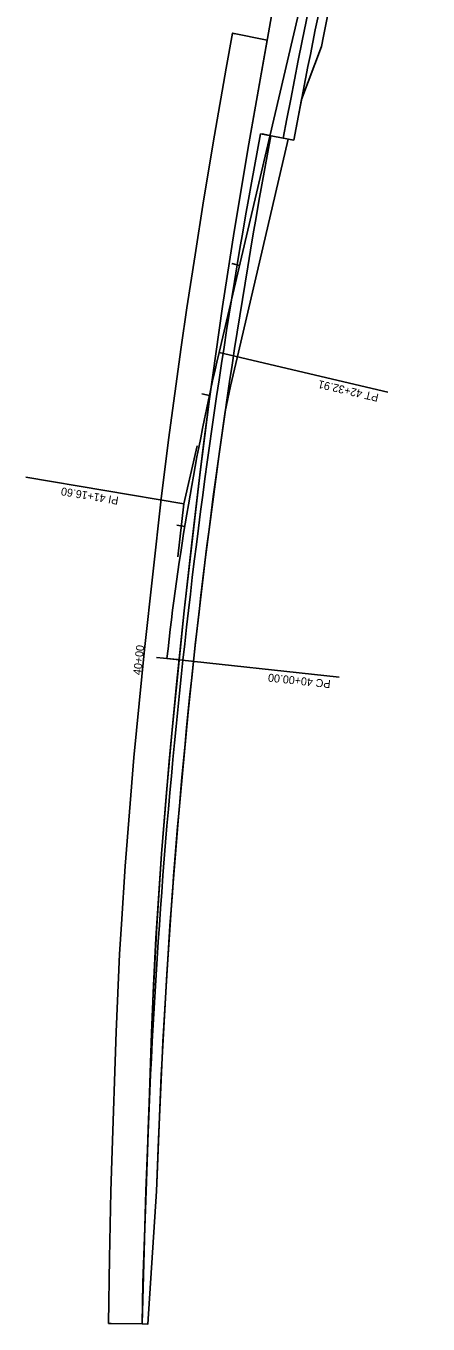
# Model space of a CAD drawing. Extents: x 1445613 to 1446340, y 2042797 to 2056486.
# Drawn here: x 1445613 to 1445914, y 2053367 to 2054340 of the extents above; entities that cross this region are included whole.
import ezdxf

# ---------------------------------------------------------------- set-up
doc = ezdxf.new("R2010")
doc.units = 0
for name, color, linetype in [('20', 7, 'Continuous'), ('Default', 7, 'Continuous'), ('R_Horz Alg', 7, 'Continuous'), ('R_Horz Alg Annot_Detour', 7, 'Continuous'), ('R_Horz Alg Stationing_Detour', 7, 'Continuous'), ('R_Proposed Road', 7, 'Continuous')]:
    doc.layers.add(name, color=color, linetype=linetype)

msp = doc.modelspace()

# ---------------------------------------------------------------- linework, layer by layer
at = {"layer": '20'}
msp.add_lwpolyline([(1445870.01, 2054502.76), (1445836.06, 2054332.52), (1445834.49, 2054324.75), (1445819.56, 2054285.22), (1445813.75, 2054254.63), (1445809.55, 2054255.41), (1445790.46, 2054173.78), (1445790.46, 2054173.78), (1445772.18, 2054095.64), (1445766.34, 2054070.08), (1445762.27, 2054051.24), (1445758, 2054021.18), (1445747.59, 2053941.98), (1445739.81, 2053875.52), (1445734.54, 2053825.65), (1445727.23, 2053747.07), (1445722.55, 2053688.35), (1445718.5, 2053629.06), (1445714.98, 2053566.67), (1445712.25, 2053505.21), (1445710.9, 2053466.32), (1445704.36, 2053366.78), (1445700.07, 2053366.83), (1445700.45, 2053397.66), (1445703.14, 2053466.51), (1445704.51, 2053512.96), (1445706.68, 2053573.23), (1445707.94, 2053608.8), (1445710.99, 2053665.29), (1445714.61, 2053719.31), (1445720.36, 2053788.85), (1445725.72, 2053846.27), (1445731.41, 2053901.64), (1445737.33, 2053952.64), (1445743.26, 2054003.64), (1445746.84, 2054032.1), (1445750.41, 2054060.55), (1445760.33, 2054129.83), (1445769.06, 2054186.05), (1445780.04, 2054251.75), (1445799.01, 2054359.02)], dxfattribs=at)
msp.add_lwpolyline([(1445674.84, 2053367.13), (1445700.07, 2053366.83), (1445700.45, 2053397.66), (1445703.14, 2053466.51), (1445704.94, 2053525.06), (1445707.1, 2053585.09), (1445708.55, 2053620.61), (1445710.38, 2053656.06), (1445714.61, 2053719.31), (1445718.26, 2053765.38), (1445722.45, 2053812.32), (1445731.41, 2053901.64), (1445743.26, 2054003.64), (1445750.41, 2054060.55), (1445760.33, 2054129.83), (1445769.06, 2054186.05), (1445780.04, 2054251.75), (1445790.18, 2054309.86), (1445793.67, 2054329.54), (1445767.66, 2054334.76), (1445763.07, 2054308.69), (1445754.39, 2054258.33), (1445746.12, 2054209.11), (1445739.66, 2054168.51), (1445733.55, 2054128.87), (1445729.18, 2054099.27), (1445719.7, 2054029.76), (1445714.16, 2053985.73), (1445701.84, 2053872.7), (1445693.83, 2053791.57), (1445687.38, 2053710.2), (1445684.44, 2053666.63), (1445683.14, 2053644.24), (1445680.49, 2053585.83), (1445677.31, 2053489.4), (1445676.65, 2053466.24), (1445675.65, 2053416.12)], close=True, dxfattribs=at)
at = {"layer": 'Default'}
for p, q in [((1445767.66, 2054334.76), (1445769.62, 2054334.36)), ((1445674.84, 2053367.13), (1445676.84, 2053367.1))]:
    msp.add_line(p, q, dxfattribs=at)
at = {"layer": 'R_Horz Alg'}
msp.add_line((1445757.73, 2054095.33), (1445849.12, 2054486.09), dxfattribs=at)
msp.add_arc((1447617.41, 2053660.4), 1909.86, 166.83661, 173.8239, dxfattribs=at)
at = {"layer": 'R_Horz Alg Annot_Detour'}
for q in [(1445741.36, 2054025.32), (1445726.9, 2053942.25)]:
    msp.add_line((1445731.18, 2053981.8), q, dxfattribs=at)
for points in [[(1445757.73, 2054095.33), (1445884.32, 2054065.73)], [(1445731.18, 2053981.8), (1445612.89, 2054001.95)], [(1445718.64, 2053865.88), (1445847.88, 2053851.89)]]:
    msp.add_lwpolyline(points, dxfattribs=at)
at = {"layer": 'R_Horz Alg Stationing_Detour'}
for points in [[(1445789.94, 2054259.4), (1445795.78, 2054258.03)], [(1445767.17, 2054162.03), (1445773.01, 2054160.66)], [(1445744.65, 2054064.49), (1445750.52, 2054063.23)], [(1445726.07, 2053965.93), (1445731.99, 2053964.97)], [(1445710.68, 2053866.74), (1445726.59, 2053865.02)]]:
    msp.add_lwpolyline(points, dxfattribs=at)
at = {"layer": 'R_Proposed Road'}
for p, q in [((1445788.69, 2054259.31), (1445813.75, 2054254.63)), ((1445702.9, 2053466.56), (1445700.07, 2053366.83)), ((1445710.9, 2053466.32), (1445704.36, 2053366.78)), ((1445700.07, 2053366.83), (1445704.36, 2053366.78))]:
    msp.add_line(p, q, dxfattribs=at)
for radius, start, end in [(5179.21, 164.16667, 169.4239), (5171.21, 166.10725, 169.4239), (5196.71, 169.4239, 178.2239), (5188.71, 169.4239, 178.2239)]:
    msp.add_arc((1450897.11, 2053305.5), radius, start, end, dxfattribs=at)

# ---------------------------------------------------------------- texts
at = {"layer": 'R_Horz Alg Annot_Detour'}
for s, rotation, p in [('PT 42+32.91', 166.83661, (1445877.79, 2054064.17)), ('PI 41+16.60', 170.33026, (1445682.66, 2053987.02)), ('PC 40+00.00', 173.8239, (1445841.59, 2053849.55))]:
    msp.add_text(s, height=6, rotation=rotation, dxfattribs=at).set_placement(p)
at = {"layer": 'R_Horz Alg Stationing_Detour'}
msp.add_text('40+00', height=6, rotation=83.8239, dxfattribs=at).set_placement((1445699.16, 2053853.25))

doc.saveas('drawing.dxf')
